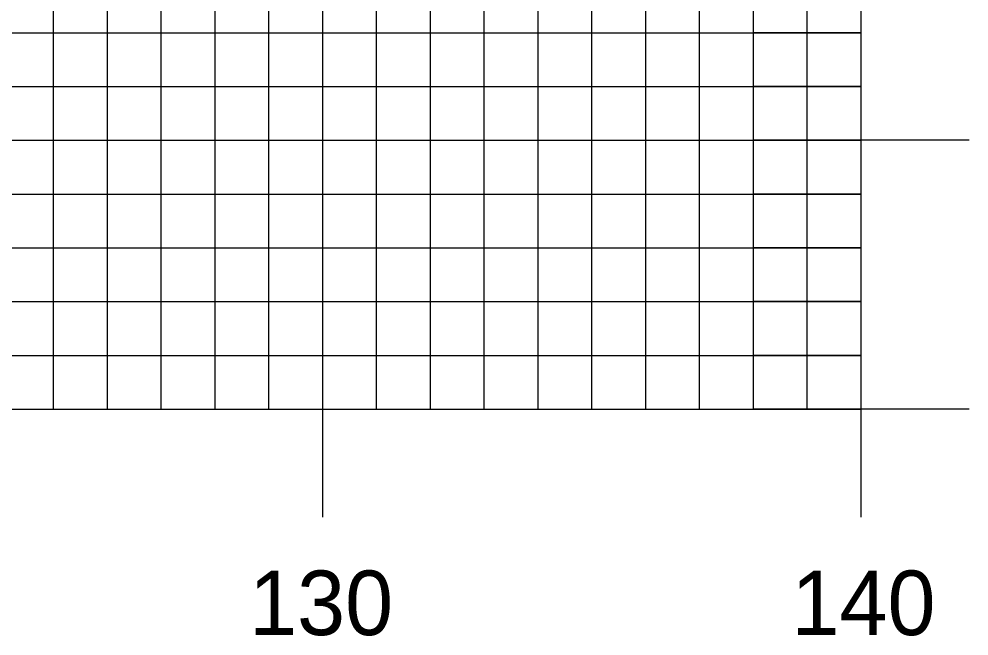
# Model space of a CAD drawing. Extents: x 1760610 to 1760954, y 442591 to 442811.
# Drawn here: x 1760900.57 to 1760918.22, y 442659.45 to 442670.92 of the extents above; entities that cross this region are included whole.
import ezdxf

# ---------------------------------------------------------------- set-up
doc = ezdxf.new("R2010")
doc.units = 0
for name, color, linetype in [('H_V ANNOTATION', 7, 'Continuous'), ('MAJOR', 7, 'Continuous'), ('MINOR', 7, 'Continuous')]:
    doc.layers.add(name, color=color, linetype=linetype)

msp = doc.modelspace()

# ---------------------------------------------------------------- linework, layer by layer
at = {"layer": 'MAJOR'}
for p, q in [((1760906.214, 442663.665), (1760906.214, 442698.665)), ((1760916.214, 442663.665), (1760916.214, 442698.665)), ((1760916.214, 442663.665), (1760916.214, 442698.665)), ((1760636.214, 442668.665), (1760916.214, 442668.665)), ((1760918.218, 442668.665), (1760914.21, 442668.665)), ((1760636.214, 442663.665), (1760916.214, 442663.665)), ((1760636.214, 442663.665), (1760916.214, 442663.665)), ((1760906.214, 442661.661), (1760906.214, 442663.665)), ((1760918.218, 442663.665), (1760914.21, 442663.665)), ((1760916.214, 442661.661), (1760916.214, 442663.665))]:
    msp.add_line(p, q, dxfattribs=at)
at = {"layer": 'MINOR'}
for p, q in [((1760901.214, 442663.665), (1760901.214, 442698.665)), ((1760902.214, 442663.665), (1760902.214, 442698.665)), ((1760903.214, 442663.665), (1760903.214, 442698.665)), ((1760904.214, 442663.665), (1760904.214, 442698.665)), ((1760905.214, 442663.665), (1760905.214, 442698.665)), ((1760907.214, 442663.665), (1760907.214, 442698.665)), ((1760908.214, 442663.665), (1760908.214, 442698.665)), ((1760909.214, 442663.665), (1760909.214, 442698.665)), ((1760910.214, 442663.665), (1760910.214, 442698.665)), ((1760911.214, 442663.665), (1760911.214, 442698.665)), ((1760912.214, 442663.665), (1760912.214, 442698.665)), ((1760913.214, 442663.665), (1760913.214, 442698.665)), ((1760914.214, 442663.665), (1760914.214, 442698.665)), ((1760915.214, 442663.665), (1760915.214, 442698.665)), ((1760636.214, 442670.665), (1760916.214, 442670.665)), ((1760916.214, 442670.665), (1760914.21, 442670.665)), ((1760636.214, 442669.665), (1760916.214, 442669.665)), ((1760916.214, 442669.665), (1760914.21, 442669.665)), ((1760636.214, 442667.665), (1760916.214, 442667.665)), ((1760916.214, 442667.665), (1760914.21, 442667.665)), ((1760636.214, 442666.665), (1760916.214, 442666.665)), ((1760916.214, 442666.665), (1760914.21, 442666.665)), ((1760636.214, 442665.665), (1760916.214, 442665.665)), ((1760916.214, 442665.665), (1760914.21, 442665.665)), ((1760636.214, 442664.665), (1760916.214, 442664.665)), ((1760916.214, 442664.665), (1760914.21, 442664.665))]:
    msp.add_line(p, q, dxfattribs=at)

# ---------------------------------------------------------------- texts
at = {"layer": 'H_V ANNOTATION'}
for s, p in [('130', (1760904.844, 442659.465)), ('140', (1760914.919, 442659.465))]:
    msp.add_text(s, height=1.2, dxfattribs=at).set_placement(p)

doc.saveas('drawing.dxf')
